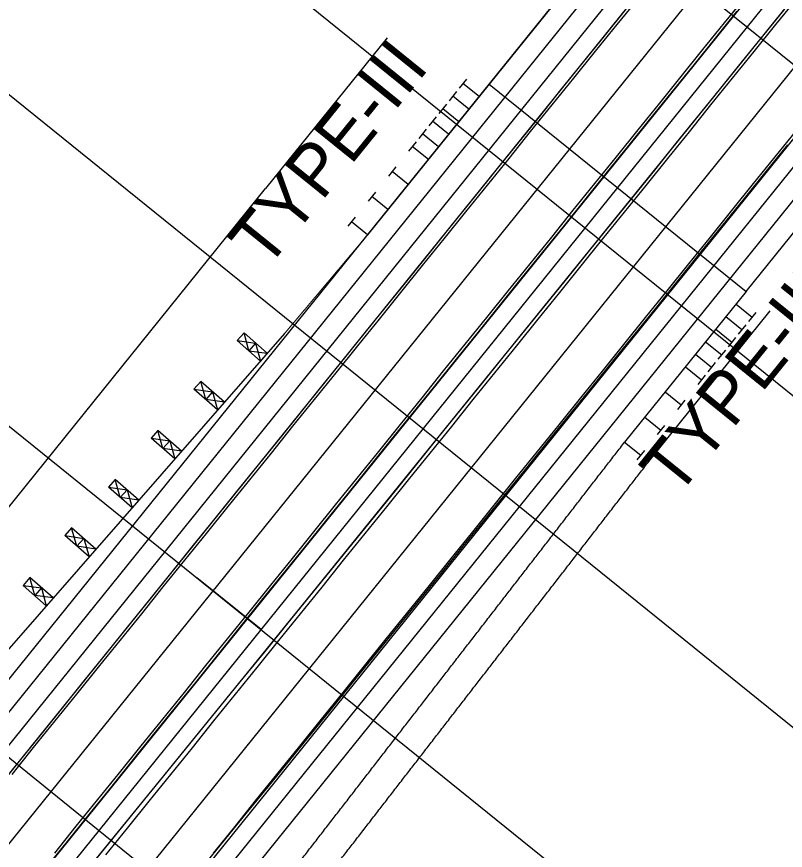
# Model space of a CAD drawing. Extents: x 2293233 to 2294507, y 892788 to 894229.
# Drawn here: x 2293794 to 2293868.5, y 893375.3 to 893456.1 of the extents above; entities that cross this region are included whole.
import ezdxf

# ---------------------------------------------------------------- set-up
doc = ezdxf.new("R2010")
doc.units = 0
for name, color, linetype in [('COGO Default Curve', 7, 'Continuous'), ('Prop EOT', 7, 'Continuous'), ('Prop Guardrail', 7, 'Continuous'), ('Prop Guardrail Anchor Unit CELL', 7, 'Continuous'), ('Prop Horizontal Alignment', 7, 'Continuous'), ('Prop Paved Shoulder', 7, 'Continuous'), ('Prop Roadway Bridge', 7, 'Continuous'), ('Prop Structure Anchor Unit CELL', 7, 'Continuous'), ('Scratch_Level_4', 7, 'Continuous'), ('Scratch_Level_5', 7, 'Continuous')]:
    doc.layers.add(name, color=color, linetype=linetype)

msp = doc.modelspace()

# ---------------------------------------------------------------- linework, layer by layer
at = {"layer": 'COGO Default Curve'}
for p, q in [((2293758.367, 893332.688), (2294065.501, 893713.269)), ((2293767.706, 893325.152), (2294074.839, 893705.733))]:
    msp.add_line(p, q, dxfattribs=at)
for points in [[(2294073.937, 893697.861), (2293868.785, 893443.627), (2293792.195, 893348.658), (2293779.831, 893333.364), (2293770.785, 893322.246), (2293765.286, 893315.548), (2293760.602, 893309.906), (2293756.094, 893304.552), (2293751.765, 893299.483), (2293746.961, 893293.942), (2293742.337, 893288.687), (2293737.451, 893283.218), (2293732.748, 893278.033), (2293727.78, 893272.638), (2293722.771, 893267.281), (2293717.72, 893261.963), (2293712.861, 893256.923), (2293707.731, 893251.681), (2293702.797, 893246.714), (2293697.587, 893241.549), (2293692.578, 893236.657)], [(2294044.74, 893680.704), (2293954.06, 893568.406), (2293770.667, 893341.162), (2293761.426, 893329.772), (2293756.77, 893324.106), (2293752.509, 893318.978), (2293748.219, 893313.876), (2293744.114, 893309.053), (2293739.98, 893304.257), (2293735.815, 893299.486), (2293731.619, 893294.743), (2293727.393, 893290.028), (2293722.91, 893285.094), (2293718.62, 893280.437), (2293714.298, 893275.808), (2293709.946, 893271.209), (2293705.563, 893266.639), (2293701.149, 893262.098), (2293696.705, 893257.587), (2293692.231, 893253.107), (2293687.727, 893248.656), (2293683.193, 893244.235), (2293678.629, 893239.845)], [(2293680.138, 893237.736), (2293686.343, 893243.782), (2293692.264, 893249.643), (2293698.138, 893255.551), (2293703.964, 893261.507), (2293709.741, 893267.511), (2293715.469, 893273.562), (2293720.919, 893279.417), (2293726.546, 893285.562), (2293732.123, 893291.753), (2293737.873, 893298.236), (2293743.796, 893305.012), (2293749.892, 893312.079), (2293756.38, 893319.69), (2293763.259, 893327.843), (2293770.528, 893336.54), (2293778.402, 893346.033), (2293786.881, 893356.323), (2293796.389, 893367.925), (2293808.608, 893382.907), (2293822.69, 893400.239), (2293860.227, 893446.616), (2293932.887, 893536.606), (2294046.751, 893677.72)], [(2293687.135, 893261.626), (2293692.081, 893266.58), (2293696.991, 893271.57), (2293701.867, 893276.593), (2293706.708, 893281.65), (2293711.514, 893286.74), (2293716.286, 893291.863), (2293721.024, 893297.016), (2293725.728, 893302.2), (2293730.622, 893307.663), (2293735.481, 893313.157), (2293740.305, 893318.68), (2293745.098, 893324.231), (2293750.075, 893330.063), (2293755.02, 893335.922), (2293760.15, 893342.06), (2293765.463, 893348.479), (2293771.172, 893355.436), (2293778.958, 893365), (2293789.02, 893377.439), (2293934.914, 893558.239), (2293982.187, 893616.889)], [(2293854.282, 893457.91), (2293852.189, 893455.316), (2293850.095, 893452.721), (2293848.002, 893450.127), (2293845.908, 893447.533), (2293843.814, 893444.938), (2293841.721, 893442.344), (2293839.627, 893439.75), (2293837.534, 893437.156), (2293835.44, 893434.561), (2293833.346, 893431.967), (2293831.253, 893429.373), (2293829.159, 893426.778), (2293827.065, 893424.184), (2293824.972, 893421.59), (2293822.878, 893418.996), (2293820.785, 893416.401), (2293818.691, 893413.807), (2293816.597, 893411.213), (2293814.504, 893408.618), (2293812.41, 893406.024), (2293810.317, 893403.43), (2293808.223, 893400.836), (2293806.129, 893398.241), (2293804.036, 893395.647), (2293801.942, 893393.053), (2293799.848, 893390.458), (2293797.755, 893387.864), (2293795.661, 893385.27), (2293793.568, 893382.676)], [(2293864.695, 893458.074), (2293862.602, 893455.48), (2293860.508, 893452.886), (2293858.414, 893450.291), (2293856.321, 893447.697), (2293854.227, 893445.103), (2293852.134, 893442.509), (2293850.04, 893439.914), (2293847.946, 893437.32), (2293845.853, 893434.726), (2293843.759, 893432.131), (2293841.666, 893429.537), (2293839.572, 893426.943), (2293837.478, 893424.349), (2293835.385, 893421.754), (2293833.291, 893419.16), (2293831.197, 893416.566), (2293829.104, 893413.971), (2293827.01, 893411.377), (2293824.917, 893408.783), (2293822.823, 893406.189), (2293820.729, 893403.594), (2293818.636, 893401), (2293816.542, 893398.406), (2293814.449, 893395.811), (2293812.355, 893393.217), (2293810.261, 893390.623), (2293808.168, 893388.029), (2293806.074, 893385.434), (2293803.98, 893382.84), (2293801.887, 893380.246), (2293799.793, 893377.651), (2293797.7, 893375.057)], [(2293802.699, 893374.882), (2293804.792, 893377.476), (2293806.885, 893380.07), (2293808.979, 893382.664), (2293811.072, 893385.258), (2293813.166, 893387.852), (2293815.259, 893390.446), (2293817.353, 893393.041), (2293819.446, 893395.635), (2293821.54, 893398.229), (2293823.633, 893400.823), (2293825.727, 893403.417), (2293827.82, 893406.012), (2293829.914, 893408.606), (2293832.007, 893411.2), (2293834.101, 893413.794), (2293836.195, 893416.389), (2293838.288, 893418.983), (2293840.382, 893421.577), (2293842.475, 893424.171), (2293844.569, 893426.766), (2293846.663, 893429.36), (2293848.756, 893431.954), (2293850.85, 893434.549), (2293852.943, 893437.143), (2293855.037, 893439.737), (2293857.131, 893442.331), (2293859.224, 893444.926), (2293861.318, 893447.52), (2293863.412, 893450.114), (2293865.505, 893452.708), (2293867.599, 893455.303), (2293869.692, 893457.897)], [(2293853.036, 893456.765), (2293850.943, 893454.17), (2293848.849, 893451.576), (2293846.755, 893448.982), (2293844.662, 893446.387), (2293842.568, 893443.793), (2293840.475, 893441.199), (2293838.381, 893438.604), (2293836.287, 893436.01), (2293834.194, 893433.416), (2293832.1, 893430.822), (2293830.007, 893428.227), (2293827.913, 893425.633), (2293825.819, 893423.039), (2293823.726, 893420.444), (2293821.632, 893417.85), (2293819.539, 893415.256), (2293817.445, 893412.661), (2293815.351, 893410.067), (2293813.258, 893407.473), (2293811.164, 893404.879), (2293809.071, 893402.284), (2293806.977, 893399.69), (2293804.883, 893397.096), (2293802.79, 893394.501), (2293800.696, 893391.907), (2293798.603, 893389.313), (2293796.509, 893386.719), (2293794.415, 893384.124), (2293792.321, 893381.529)], [(2293863.838, 893456.615), (2293861.745, 893454.021), (2293859.651, 893451.426), (2293857.557, 893448.832), (2293855.464, 893446.238), (2293853.37, 893443.644), (2293851.277, 893441.049), (2293849.183, 893438.455), (2293847.089, 893435.861), (2293844.996, 893433.266), (2293842.902, 893430.672), (2293840.809, 893428.078), (2293838.715, 893425.483), (2293836.621, 893422.889), (2293834.528, 893420.295), (2293832.434, 893417.701), (2293830.341, 893415.106), (2293828.247, 893412.512), (2293826.153, 893409.918), (2293824.06, 893407.323), (2293821.966, 893404.729), (2293819.873, 893402.135), (2293817.779, 893399.54), (2293815.685, 893396.946), (2293813.592, 893394.352), (2293811.498, 893391.758), (2293809.405, 893389.163), (2293807.311, 893386.569), (2293805.217, 893383.975), (2293803.124, 893381.38), (2293801.03, 893378.786), (2293798.935, 893376.191), (2293796.841, 893373.596)], [(2293801.283, 893373.918), (2293803.389, 893376.5), (2293805.494, 893379.083), (2293807.599, 893381.667), (2293809.702, 893384.252), (2293811.805, 893386.837), (2293813.907, 893389.423), (2293816.009, 893392.009), (2293818.11, 893394.596), (2293820.211, 893397.183), (2293822.311, 893399.771), (2293824.41, 893402.36), (2293826.509, 893404.949), (2293828.608, 893407.538), (2293830.707, 893410.127), (2293832.805, 893412.717), (2293834.902, 893415.308), (2293837, 893417.898), (2293839.097, 893420.489), (2293841.194, 893423.08), (2293843.291, 893425.671), (2293845.387, 893428.263), (2293847.484, 893430.854), (2293849.58, 893433.446), (2293851.676, 893436.038), (2293853.772, 893438.63), (2293855.867, 893441.223), (2293857.963, 893443.815), (2293860.058, 893446.408), (2293862.153, 893449), (2293864.248, 893451.593), (2293866.343, 893454.186), (2293868.438, 893456.779)], [(2293813.108, 893375.043), (2293815.202, 893377.637), (2293817.296, 893380.232), (2293819.39, 893382.826), (2293821.483, 893385.421), (2293823.577, 893388.015), (2293825.671, 893390.61), (2293827.764, 893393.204), (2293829.858, 893395.798), (2293831.952, 893398.393), (2293834.045, 893400.987), (2293836.139, 893403.581), (2293838.233, 893406.176), (2293840.326, 893408.77), (2293842.42, 893411.364), (2293844.514, 893413.959), (2293846.607, 893416.553), (2293848.701, 893419.147), (2293850.795, 893421.741), (2293852.888, 893424.336), (2293854.982, 893426.93), (2293857.075, 893429.524), (2293859.169, 893432.119), (2293861.263, 893434.713), (2293863.356, 893437.307), (2293865.45, 893439.901), (2293867.543, 893442.496), (2293869.637, 893445.09)], [(2293812.084, 893373.714), (2293814.19, 893376.3), (2293816.295, 893378.887), (2293818.4, 893381.474), (2293820.503, 893384.061), (2293822.606, 893386.649), (2293824.709, 893389.238), (2293826.81, 893391.827), (2293828.911, 893394.416), (2293831.012, 893397.006), (2293833.112, 893399.596), (2293835.212, 893402.186), (2293837.311, 893404.776), (2293839.41, 893407.367), (2293841.508, 893409.958), (2293843.606, 893412.55), (2293845.704, 893415.141), (2293847.802, 893417.733), (2293849.899, 893420.325), (2293851.996, 893422.917), (2293854.093, 893425.509), (2293856.189, 893428.101), (2293858.285, 893430.694), (2293860.382, 893433.286), (2293862.478, 893435.879), (2293864.573, 893438.472), (2293866.669, 893441.065), (2293868.764, 893443.658)]]:
    msp.add_lwpolyline(points, dxfattribs=at)
at = {"layer": 'Prop EOT'}
for p, q in [((2293753.698, 893336.456), (2294060.831, 893717.037)), ((2293753.698, 893336.456), (2294060.831, 893717.037)), ((2293772.375, 893321.384), (2294079.508, 893701.965))]:
    msp.add_line(p, q, dxfattribs=at)
at = {"layer": 'Prop Guardrail'}
for points in [[(2293828.05, 893434.958), (2293827.833, 893434.7), (2293827.724, 893434.57), (2293827.616, 893434.441), (2293827.507, 893434.312), (2293827.398, 893434.182), (2293827.289, 893434.053), (2293827.181, 893433.924), (2293827.072, 893433.794), (2293826.963, 893433.665), (2293826.855, 893433.536), (2293826.746, 893433.406), (2293826.637, 893433.277), (2293826.528, 893433.148), (2293826.42, 893433.018), (2293826.311, 893432.889), (2293826.202, 893432.76), (2293826.094, 893432.63), (2293825.985, 893432.501), (2293825.876, 893432.372), (2293825.767, 893432.242), (2293825.659, 893432.113), (2293825.55, 893431.984), (2293825.441, 893431.854), (2293825.333, 893431.725), (2293825.224, 893431.596), (2293825.115, 893431.466), (2293825.006, 893431.337), (2293824.898, 893431.208), (2293824.789, 893431.078), (2293824.68, 893430.949), (2293824.572, 893430.82), (2293824.463, 893430.691), (2293824.354, 893430.561), (2293824.245, 893430.432), (2293824.137, 893430.303), (2293824.028, 893430.173), (2293823.919, 893430.044), (2293823.811, 893429.915), (2293823.702, 893429.785), (2293823.593, 893429.656), (2293823.484, 893429.527), (2293823.376, 893429.397), (2293823.267, 893429.268), (2293823.158, 893429.139), (2293823.05, 893429.009), (2293822.941, 893428.88), (2293822.832, 893428.751), (2293822.723, 893428.621), (2293822.615, 893428.492), (2293822.506, 893428.363), (2293822.397, 893428.233), (2293822.289, 893428.104), (2293822.18, 893427.975), (2293822.071, 893427.845), (2293821.962, 893427.716), (2293821.854, 893427.587), (2293821.745, 893427.457), (2293821.636, 893427.328), (2293821.528, 893427.199), (2293821.419, 893427.069), (2293821.31, 893426.94), (2293821.201, 893426.811), (2293821.093, 893426.681), (2293820.984, 893426.552), (2293820.875, 893426.423), (2293820.767, 893426.293), (2293820.658, 893426.164), (2293820.549, 893426.035), (2293820.44, 893425.905), (2293820.332, 893425.776), (2293820.223, 893425.647), (2293820.114, 893425.517), (2293820.006, 893425.388)], [(2293822.33, 893375.324), (2293822.744, 893375.858), (2293823.158, 893376.392), (2293823.572, 893376.927), (2293823.985, 893377.461), (2293824.399, 893377.995), (2293824.813, 893378.53), (2293825.227, 893379.064), (2293825.641, 893379.598), (2293826.055, 893380.133), (2293826.468, 893380.667), (2293826.882, 893381.201), (2293827.296, 893381.735), (2293827.71, 893382.27), (2293828.124, 893382.804), (2293828.537, 893383.338), (2293828.951, 893383.873), (2293829.365, 893384.407), (2293829.779, 893384.941), (2293830.193, 893385.476), (2293830.607, 893386.01), (2293831.02, 893386.544), (2293831.434, 893387.078), (2293831.848, 893387.613), (2293832.262, 893388.147), (2293832.676, 893388.681), (2293833.089, 893389.216), (2293833.503, 893389.75), (2293833.917, 893390.284), (2293834.331, 893390.819), (2293834.745, 893391.353), (2293835.159, 893391.887), (2293835.572, 893392.421), (2293835.986, 893392.956), (2293836.4, 893393.49), (2293836.814, 893394.024), (2293837.228, 893394.559), (2293837.641, 893395.093), (2293838.055, 893395.627), (2293838.469, 893396.161), (2293838.883, 893396.696), (2293839.297, 893397.23), (2293839.711, 893397.764), (2293840.124, 893398.299), (2293840.538, 893398.833), (2293840.952, 893399.367), (2293841.366, 893399.902), (2293841.78, 893400.436), (2293842.193, 893400.97), (2293842.607, 893401.504), (2293843.021, 893402.039), (2293843.435, 893402.573), (2293843.849, 893403.107), (2293844.263, 893403.642), (2293844.676, 893404.176), (2293845.09, 893404.71), (2293845.504, 893405.245), (2293845.918, 893405.779), (2293846.332, 893406.313), (2293846.745, 893406.847), (2293847.159, 893407.382), (2293847.573, 893407.916), (2293847.987, 893408.45), (2293848.401, 893408.985), (2293848.815, 893409.519), (2293849.228, 893410.053), (2293849.642, 893410.588), (2293850.056, 893411.122), (2293850.47, 893411.656), (2293850.884, 893412.19), (2293851.297, 893412.725), (2293851.711, 893413.259), (2293852.125, 893413.793), (2293852.953, 893414.862)], [(2293791.708, 893335.786), (2293792.121, 893336.32), (2293792.535, 893336.854), (2293792.949, 893337.389), (2293793.363, 893337.923), (2293793.777, 893338.457), (2293794.19, 893338.992), (2293794.604, 893339.526), (2293795.018, 893340.06), (2293795.432, 893340.595), (2293795.846, 893341.129), (2293796.26, 893341.663), (2293796.673, 893342.197), (2293797.087, 893342.732), (2293797.501, 893343.266), (2293797.915, 893343.8), (2293798.329, 893344.335), (2293798.742, 893344.869), (2293799.156, 893345.403), (2293799.57, 893345.938), (2293799.984, 893346.472), (2293800.398, 893347.006), (2293800.812, 893347.54), (2293801.225, 893348.075), (2293801.639, 893348.609), (2293802.053, 893349.143), (2293802.467, 893349.678), (2293802.881, 893350.212), (2293803.294, 893350.746), (2293803.708, 893351.28), (2293804.122, 893351.815), (2293804.536, 893352.349), (2293804.95, 893352.883), (2293805.364, 893353.418), (2293805.777, 893353.952), (2293806.191, 893354.486), (2293806.605, 893355.021), (2293807.019, 893355.555), (2293807.433, 893356.089), (2293807.846, 893356.623), (2293808.26, 893357.158), (2293808.674, 893357.692), (2293809.088, 893358.226), (2293809.502, 893358.761), (2293809.916, 893359.295), (2293810.329, 893359.829), (2293810.743, 893360.364), (2293811.157, 893360.898), (2293811.571, 893361.432), (2293811.985, 893361.966), (2293812.398, 893362.501), (2293812.812, 893363.035), (2293813.226, 893363.569), (2293813.64, 893364.104), (2293814.054, 893364.638), (2293814.468, 893365.172), (2293814.881, 893365.707), (2293815.295, 893366.241), (2293815.709, 893366.775), (2293816.123, 893367.309), (2293816.537, 893367.844), (2293816.951, 893368.378), (2293817.364, 893368.912), (2293817.778, 893369.447), (2293818.192, 893369.981), (2293818.606, 893370.515), (2293819.02, 893371.05), (2293819.433, 893371.584), (2293819.847, 893372.118), (2293820.261, 893372.652), (2293820.675, 893373.187), (2293821.089, 893373.721), (2293821.503, 893374.255), (2293821.916, 893374.79), (2293822.33, 893375.324)]]:
    msp.add_spline(points, degree=3, dxfattribs=at)
at = {"layer": 'Prop Guardrail Anchor Unit CELL'}
for p, q in [((2293820.006, 893425.388), (2293789.214, 893390.209)), ((2293816.074, 893425.451), (2293815.415, 893424.698)), ((2293818.331, 893423.475), (2293816.074, 893425.451)), ((2293816.543, 893423.71), (2293816.074, 893425.451)), ((2293817.672, 893422.722), (2293815.415, 893424.698)), ((2293815.415, 893424.698), (2293817.202, 893424.463)), ((2293817.202, 893424.463), (2293816.543, 893423.71)), ((2293817.202, 893424.463), (2293817.672, 893422.722)), ((2293817.672, 893422.722), (2293816.543, 893423.71)), ((2293816.543, 893423.71), (2293818.331, 893423.475)), ((2293818.331, 893423.475), (2293817.672, 893422.722)), ((2293811.884, 893420.744), (2293811.225, 893419.991)), ((2293814.181, 893418.733), (2293811.884, 893420.744)), ((2293812.373, 893418.986), (2293811.884, 893420.744)), ((2293813.522, 893417.981), (2293811.225, 893419.991)), ((2293811.225, 893419.991), (2293813.032, 893419.738)), ((2293813.032, 893419.738), (2293812.373, 893418.986)), ((2293813.032, 893419.738), (2293813.522, 893417.981)), ((2293814.181, 893418.733), (2293812.373, 893418.986)), ((2293807.738, 893415.999), (2293807.079, 893415.247)), ((2293810.031, 893413.992), (2293807.738, 893415.999)), ((2293808.225, 893414.243), (2293807.738, 893415.999)), ((2293809.372, 893413.239), (2293807.079, 893415.247)), ((2293807.079, 893415.247), (2293808.883, 893414.995)), ((2293808.883, 893414.995), (2293808.225, 893414.243)), ((2293808.883, 893414.995), (2293809.372, 893413.239)), ((2293810.031, 893413.992), (2293808.225, 893414.243)), ((2293803.597, 893411.25), (2293802.938, 893410.497)), ((2293805.222, 893408.498), (2293802.938, 893410.497)), ((2293802.938, 893410.497), (2293804.738, 893410.25)), ((2293805.881, 893409.25), (2293803.597, 893411.25)), ((2293804.079, 893409.498), (2293803.597, 893411.25)), ((2293804.738, 893410.25), (2293804.079, 893409.498)), ((2293804.738, 893410.25), (2293805.222, 893408.498)), ((2293805.881, 893409.25), (2293804.079, 893409.498)), ((2293805.881, 893409.25), (2293805.222, 893408.498)), ((2293799.37, 893406.576), (2293798.711, 893405.823)), ((2293801.73, 893404.509), (2293799.37, 893406.576)), ((2293799.892, 893404.79), (2293799.37, 893406.576)), ((2293801.072, 893403.756), (2293798.711, 893405.823)), ((2293798.711, 893405.823), (2293800.551, 893405.542)), ((2293800.551, 893405.542), (2293799.892, 893404.79)), ((2293800.551, 893405.542), (2293801.072, 893403.756)), ((2293801.73, 893404.509), (2293799.892, 893404.79)), ((2293795.323, 893401.743), (2293794.664, 893400.99)), ((2293797.58, 893399.767), (2293795.323, 893401.743)), ((2293795.792, 893400.003), (2293795.323, 893401.743)), ((2293796.921, 893399.015), (2293794.664, 893400.99)), ((2293794.664, 893400.99), (2293796.451, 893400.756)), ((2293796.451, 893400.756), (2293795.792, 893400.003)), ((2293797.58, 893399.767), (2293795.792, 893400.003)), ((2293796.451, 893400.756), (2293796.921, 893399.015))]:
    msp.add_line(p, q, dxfattribs=at)
at = {"layer": 'Prop Horizontal Alignment'}
for p, q in [((2293763.036, 893328.92), (2294070.17, 893709.501)), ((2293763.036, 893328.92), (2294070.17, 893709.501)), ((2293817.736, 893396.7), (2293811.51, 893401.725))]:
    msp.add_line(p, q, dxfattribs=at)
at = {"layer": 'Prop Paved Shoulder'}
for p, q in [((2293752.142, 893337.712), (2294059.275, 893718.293)), ((2293773.931, 893320.128), (2294081.065, 893700.709))]:
    msp.add_line(p, q, dxfattribs=at)
at = {"layer": 'Prop Roadway Bridge'}
for p, q in [((2293967.853, 893608.194), (2293839.826, 893449.55)), ((2293864.728, 893429.453), (2293992.755, 893588.097)), ((2293839.826, 893449.55), (2293864.728, 893429.453))]:
    msp.add_line(p, q, dxfattribs=at)
at = {"layer": 'Prop Structure Anchor Unit CELL'}
for p, q in [((2293837.648, 893450.035), (2293836.928, 893449.144)), ((2293839.826, 893449.55), (2293828.05, 893434.958)), ((2293838.844, 893448.334), (2293837.288, 893449.59)), ((2293836.666, 893448.82), (2293835.947, 893447.928)), ((2293837.863, 893447.118), (2293836.307, 893448.374)), ((2293835.685, 893447.604), (2293834.966, 893446.712)), ((2293836.882, 893445.902), (2293835.325, 893447.158)), ((2293834.704, 893446.388), (2293833.984, 893445.496)), ((2293835.901, 893444.686), (2293834.344, 893445.942)), ((2293833.723, 893445.172), (2293833.003, 893444.28)), ((2293834.919, 893443.47), (2293833.363, 893444.726)), ((2293832.741, 893443.956), (2293832.022, 893443.064)), ((2293833.938, 893442.254), (2293832.382, 893443.51)), ((2293830.779, 893441.524), (2293830.059, 893440.633)), ((2293831.975, 893439.822), (2293830.419, 893441.078)), ((2293828.816, 893439.092), (2293828.097, 893438.201)), ((2293830.013, 893437.39), (2293828.457, 893438.646)), ((2293826.854, 893436.66), (2293826.134, 893435.769)), ((2293828.05, 893434.958), (2293826.494, 893436.214)), ((2293864.728, 893429.453), (2293852.953, 893414.862)), ((2293863.747, 893428.237), (2293865.303, 893426.981)), ((2293865.663, 893427.427), (2293864.944, 893426.535)), ((2293862.766, 893427.021), (2293864.322, 893425.765)), ((2293864.682, 893426.211), (2293863.962, 893425.32)), ((2293861.784, 893425.805), (2293863.341, 893424.549)), ((2293860.803, 893424.589), (2293862.359, 893423.333)), ((2293863.7, 893424.995), (2293862.981, 893424.104)), ((2293862.719, 893423.779), (2293862, 893422.888)), ((2293859.822, 893423.373), (2293861.378, 893422.117)), ((2293858.84, 893422.158), (2293860.397, 893420.902)), ((2293861.738, 893422.563), (2293861.018, 893421.672)), ((2293860.757, 893421.347), (2293860.037, 893420.456)), ((2293856.878, 893419.726), (2293858.434, 893418.47)), ((2293858.794, 893418.915), (2293858.075, 893418.024)), ((2293854.915, 893417.294), (2293856.472, 893416.038)), ((2293856.831, 893416.483), (2293856.112, 893415.592)), ((2293852.953, 893414.862), (2293854.509, 893413.606)), ((2293854.869, 893414.052), (2293854.149, 893413.16))]:
    msp.add_line(p, q, dxfattribs=at)
at = {"layer": 'Scratch_Level_4'}
for p, q in [((2293708.319, 893261.117), (2294130.816, 893784.65)), ((2293748.107, 893549.268), (2293981.567, 893360.863)), ((2293732.407, 893529.813), (2293965.867, 893341.408)), ((2293716.706, 893510.358), (2293950.166, 893321.953)), ((2293701.006, 893490.903), (2293934.466, 893302.498)), ((2293685.306, 893471.448), (2293918.766, 893283.043))]:
    msp.add_line(p, q, dxfattribs=at)
at = {"layer": 'Scratch_Level_5'}
for p, q in [((2293750.585, 893338.968), (2293936.675, 893569.559)), ((2293829.948, 893454.013), (2293818.173, 893439.422)), ((2293676.842, 893264.332), (2293818.173, 893439.422)), ((2293855.287, 893412.978), (2293867.063, 893427.569))]:
    msp.add_line(p, q, dxfattribs=at)
msp.add_spline([(2293824.702, 893373.487), (2293825.116, 893374.021), (2293825.53, 893374.555), (2293825.943, 893375.09), (2293826.357, 893375.624), (2293826.771, 893376.158), (2293827.185, 893376.693), (2293827.599, 893377.227), (2293828.013, 893377.761), (2293828.426, 893378.296), (2293828.84, 893378.83), (2293829.254, 893379.364), (2293829.668, 893379.898), (2293830.082, 893380.433), (2293830.495, 893380.967), (2293830.909, 893381.501), (2293831.323, 893382.036), (2293831.737, 893382.57), (2293832.151, 893383.104), (2293832.565, 893383.639), (2293832.978, 893384.173), (2293833.392, 893384.707), (2293833.806, 893385.241), (2293834.22, 893385.776), (2293834.634, 893386.31), (2293835.047, 893386.844), (2293835.461, 893387.379), (2293835.875, 893387.913), (2293836.289, 893388.447), (2293836.703, 893388.982), (2293837.117, 893389.516), (2293837.53, 893390.05), (2293837.944, 893390.584), (2293838.358, 893391.119), (2293838.772, 893391.653), (2293839.186, 893392.187), (2293839.599, 893392.722), (2293840.013, 893393.256), (2293840.427, 893393.79), (2293840.841, 893394.325), (2293841.255, 893394.859), (2293841.669, 893395.393), (2293842.082, 893395.927), (2293842.496, 893396.462), (2293842.91, 893396.996), (2293843.324, 893397.53), (2293843.738, 893398.065), (2293844.151, 893398.599), (2293844.565, 893399.133), (2293844.979, 893399.667), (2293845.393, 893400.202), (2293845.807, 893400.736), (2293846.221, 893401.27), (2293846.634, 893401.805), (2293847.048, 893402.339), (2293847.462, 893402.873), (2293847.876, 893403.408), (2293848.29, 893403.942), (2293848.703, 893404.476), (2293849.117, 893405.01), (2293849.531, 893405.545), (2293849.945, 893406.079), (2293850.359, 893406.613), (2293850.773, 893407.148), (2293851.186, 893407.682), (2293851.6, 893408.216), (2293852.014, 893408.751), (2293852.428, 893409.285), (2293852.842, 893409.819), (2293853.255, 893410.353), (2293853.669, 893410.888), (2293854.083, 893411.422), (2293854.497, 893411.956), (2293855.325, 893413.025)], degree=3, dxfattribs=at)

# ---------------------------------------------------------------- texts
at = {"layer": 'Prop Structure Anchor Unit CELL'}
for p in [(2293818.236, 893431.48), (2293858.036, 893409.427)]:
    msp.add_text('TYPE-III', height=5, rotation=51.07477, dxfattribs=at).set_placement(p)

doc.saveas('drawing.dxf')
